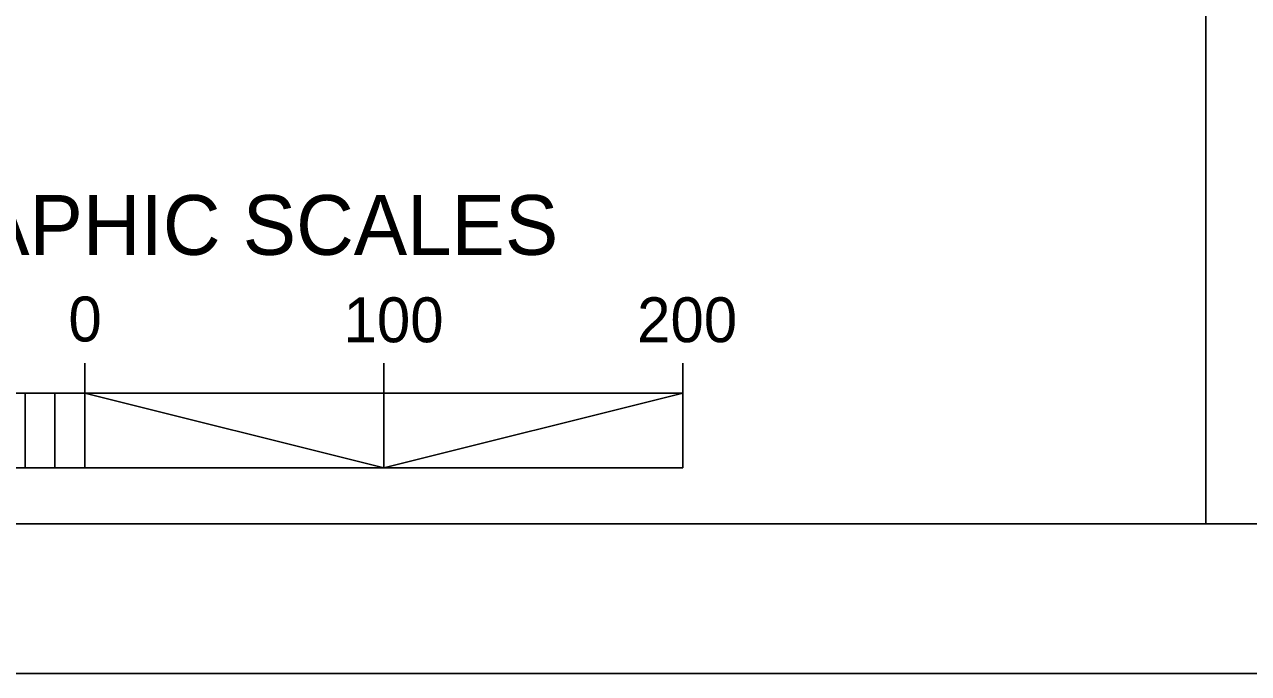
# Model space of a CAD drawing. Extents: x 1636954 to 1644154, y 841334 to 845582.
# Drawn here: x 1643059 to 1643468.4, y 841333.9 to 841551 of the extents above; entities that cross this region are included whole.
import ezdxf

# ---------------------------------------------------------------- set-up
doc = ezdxf.new("R2010")
doc.units = 0
for name, color, linetype in [('Scratch_Level_1', 7, 'Continuous'), ('Sheet Data Field CELL', 7, 'Continuous'), ('Sheet Plan And Profile CELL', 7, 'Continuous'), ('Sheet Title CELL', 7, 'Continuous')]:
    doc.layers.add(name, color=color, linetype=linetype)

msp = doc.modelspace()

# ---------------------------------------------------------------- linework, layer by layer
at = {"layer": 'Scratch_Level_1'}
msp.add_lwpolyline([(1636954.2, 841333.94), (1636954.2, 844733.94), (1644154.2, 844733.94), (1644154.2, 841333.94)], close=True, dxfattribs=at)
at = {"layer": 'Sheet Plan And Profile CELL'}
msp.add_lwpolyline([(1637004.2, 841383.94), (1637004.2, 844683.94), (1644104.2, 844683.94), (1644104.2, 841383.94)], close=True, dxfattribs=at)
for points in [[(1643454.2, 844683.94), (1643454.2, 841383.94)], [(1643454.2, 841383.94), (1643454.2, 841833.94), (1642804.2, 841833.94), (1642804.2, 841383.94)]]:
    msp.add_lwpolyline(points, dxfattribs=at)
at = {"layer": 'Sheet Title CELL'}
for p, q in [((1643079.2, 841427.69), (1643079.2, 841437.69)), ((1643179.2, 841427.72), (1643179.2, 841437.69)), ((1643279.2, 841427.72), (1643279.2, 841437.72)), ((1643279.2, 841427.72), (1642979.2, 841427.72)), ((1643079.2, 841427.69), (1643079.2, 841402.72)), ((1643179.2, 841427.72), (1643179.2, 841402.72)), ((1643279.2, 841402.72), (1643279.2, 841427.72)), ((1642979.2, 841402.72), (1643279.2, 841402.72))]:
    msp.add_line(p, q, dxfattribs=at)
for points in [[(1643059.2, 841427.72), (1643069.2, 841427.72), (1643069.2, 841402.72), (1643059.2, 841402.72)], [(1643079.2, 841427.69), (1643079.2, 841402.72), (1643179.2, 841402.72)], [(1643179.2, 841402.72), (1643279.2, 841402.72), (1643279.2, 841427.72)]]:
    msp.add_lwpolyline(points, close=True, dxfattribs=at)

# ---------------------------------------------------------------- texts
at = {"layer": 'Sheet Data Field CELL'}
for s, p in [('100', (1643165.73, 841444.72)), ('200', (1643263.93, 841444.74))]:
    msp.add_text(s, height=15, dxfattribs=at).set_placement(p)
at = {"layer": 'Sheet Title CELL'}
for s, height, p in [('GRAPHIC SCALES', 19.9992, (1643002.73, 841473.94)), ('0', 15, (1643073.7, 841444.99))]:
    msp.add_text(s, height=height, dxfattribs=at).set_placement(p)

doc.saveas('drawing.dxf')
